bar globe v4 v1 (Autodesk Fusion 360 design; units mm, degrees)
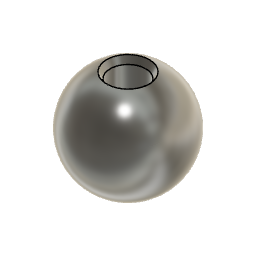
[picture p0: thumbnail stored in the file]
sketch "Sketch1" plane through (0, 0, 0) normal (0, 1, 0) x axis (1, 0, 0)
  line L1 (0, -6) -> (0, 6)
  arc A1 centre (0, 0) radius 6 clockwise from (0, 6) to (0, -6)
  point P1 (0, 0)
  point P3 (0, 0)
  vertical L1
  coincident P1 L1
  coincident P1 P3
  dimension "d1" diameter A1 = 12
revolve "Revolve1" sketch "Sketch1" AlongAngle 360
sketch "Sketch2" plane through (0, 0, 0) normal (0, 1, 0) x axis (1, 0, 0)
  line L1 (4.4181, -6.772) -> (-6.0698, -6.772)
  line L2 (4.4181, -5.5) -> (4.4181, -6.772)
  line L3 (-6.0698, -5.5) -> (4.4181, -5.5)
  line L4 (-6.0698, -6.772) -> (-6.0698, -5.5)
  point P1 (0, 0)
  horizontal L1
  vertical L2
  horizontal L3
  vertical L4
  dimension "d3" distance P1 L3 = 5.5
extrude "Extrude1" cut sketch "Sketch2" along normal blind 6 and against normal blind 14
sketch "Sketch3" plane through (0, 0, 0) normal (0, 1, 0) x axis (1, 0, 0)
  line L1 (6.3846, 5.5) -> (-5.7707, 5.5)
  line L2 (6.3846, 7.8328) -> (6.3846, 5.5)
  line L3 (-5.7707, 7.8328) -> (6.3846, 7.8328)
  line L4 (-5.7707, 5.5) -> (-5.7707, 7.8328)
  point P1 (0, 0)
  horizontal L1
  vertical L2
  horizontal L3
  vertical L4
  dimension "d8" distance P1 L1 = 5.5
extrude "Extrude2" cut sketch "Sketch3" along normal blind 13 and against normal blind 10
hole "Hole1" HoleDepth 12 HoleDiameter 4 TipAngle 118 CSDiameter 4.8 CSAngle 60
